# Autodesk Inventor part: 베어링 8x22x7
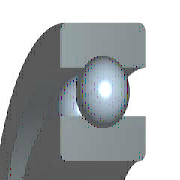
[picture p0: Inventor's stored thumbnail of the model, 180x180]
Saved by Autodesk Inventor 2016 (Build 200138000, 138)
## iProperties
IsCustomPart: 1
Created: 2012-02
Part Number: 베어링 8x22x7
Material: 강철, 연강
Description: 깊은 그루브 볼 베어링
Document SubType Name: Modeling
Standard: KS B 2023
Designer: mduedu
Standards Organization: KS
Language: ko-KR
Size Designation: 608 - 8 x 22 x 7
Categories: <MemberInstance><Categories><Category DisplayName="샤프트 부품" InternalName="7f7aeb1f-a693-4053-b835-cee3144e0d98" Mnemonic="SHFT"><Category DisplayName="베어링" Inter
Density: 7.85 g/cm^3
Appearance: 노란색
Mass: 12.145 g
Surface Area: 20.0754 cm^2
Volume: 1.54714 cm^3
Author: mduedu
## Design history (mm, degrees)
sketch "스케치" dims "d0" = 3.64 (= -0.26 x WD + 0.26 x BD)
  geometry: L1 (1.68, 7.5)-(5.32, 7.5); L2 (3.5, 7.5)-(3.5, 5.68); L3 (3.5, 7.5)-(3.5, 9.32); L4 (2.148, 6.282)-(0, 6.282); L5 (0, 4)-(7, 4); L6 (2.148, 8.718)-(0, 8.718); L7 (0, 11)-(7, 11); L8 (7, 4)-(7, 6.282); L9 (4.852, 6.282)-(7, 6.282); L10 (4.852, 8.718)-(7, 8.718); L11 (7, 11)-(7, 8.718); L12 (-1.4, 0)-(8.4, 0) reference; L13 (0, -0.3)-(0, 5.3) reference
  constraints: 22 end point, 4 point on line, 2 collinear, 2 perpendicular, 2 symmetric about line, 1 midpoint, 1 parallel, 14 other
  dimensions: "d9" = 8 diameter of L5 L12 (= WD); "d11" = 22 diameter of L7 L12 (= BD); "d12" = 7 distance between parallel lines of L8 L13 (= KB); "d13" = 12.564 diameter of L9 L12 (= 0.326 x BD + 0.674 x WD)
revolve "본체" stored, may be unused: angle "d6" = 90 deg
revolve "볼" stored, may be unused: angle "d7" = 90 deg
pattern_circular "IDS_ARRAYBALL[SIMPL:T]" dims angle "d3" = 360 deg
body "Solid1"
fillet "모깎기1" dims "d1" = 0.3 (= KRS)
other parameters: "WD" = 8 [user parameter; used in 5 equation terms], "BD" = 22 [user parameter; used in 5 equation terms], "KB" = 7 [user parameter; used in 1 equation term], "KRS" = 0.3 [user parameter; used in 1 equation term], "d4" = 0, "d5" = 0, "d8" = 0, "d14" = 0, "d15" = 0, "BBA" = 0 [user parameter], "BC0" = 1370000 [user parameter], "BC" = 3250000 [user parameter], "BR" = 11 (= 0.5 x BD) [user parameter], "WR" = 4 (= 0.5 x WD) [user parameter]
